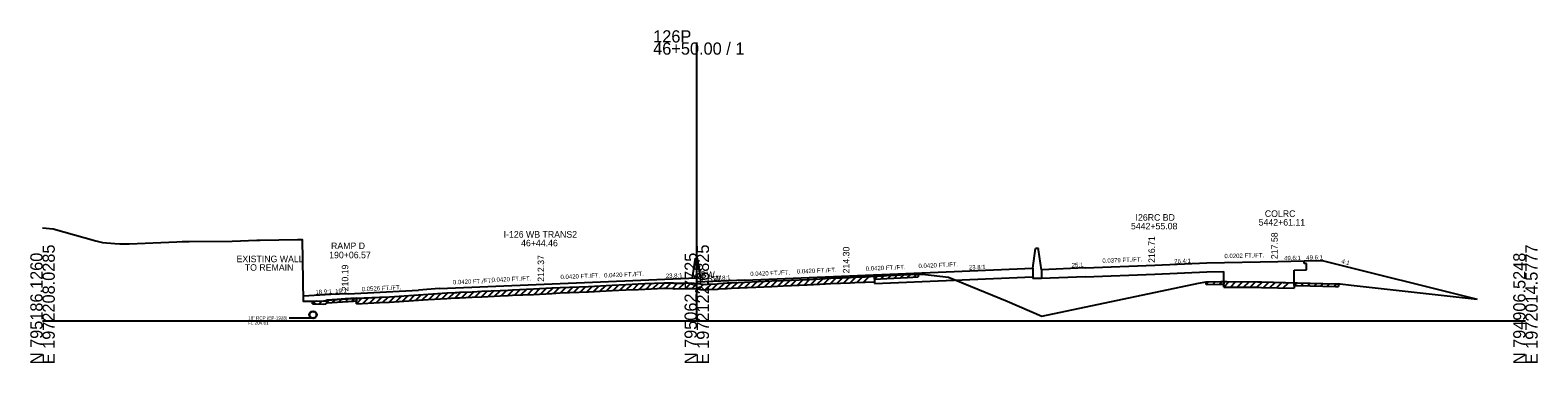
# Model space of a CAD drawing. Extents: x -161 to 1970889, y -4362 to 797231.
# Drawn here: x 997.2 to 1342.8, y 8990.3 to 9066.7 of the extents above; entities that cross this region are included whole.
import ezdxf

# ---------------------------------------------------------------- set-up
doc = ezdxf.new("R2010")
doc.units = 0
for name, color, linetype in [('RD_GPK_XS_Cell', 7, 'Continuous'), ('RD_XS_Base', 7, 'Continuous'), ('RD_XS_EarthShd', 7, 'Continuous'), ('RD_XS_ExGround', 7, 'Continuous'), ('RD_XS_ExPaveRet', 7, 'Continuous'), ('RD_XS_MedBWall', 7, 'Continuous'), ('RD_XS_Misc_Line', 7, 'Continuous'), ('RD_XS_Pave', 7, 'Continuous'), ('RD_XS_PaveOvlay', 7, 'Continuous'), ('RD_XS_PaveShd', 7, 'Continuous'), ('RD_XS_Pipe', 7, 'Continuous'), ('RD_XS_TieSlope', 7, 'Continuous'), ('RD_XS_TX_Elev_EX', 7, 'Continuous'), ('RD_XS_TX_Elev_PR', 7, 'Continuous'), ('RD_XS_TX_MkPT', 7, 'Continuous'), ('RD_XS_TX_Notes', 7, 'Continuous'), ('RD_XS_TX_Profile', 7, 'Continuous'), ('RD_XS_TX_ShdSlope', 7, 'Continuous'), ('RD_XS_TX_Slope', 7, 'Continuous'), ('RD_XS_TX_Station', 7, 'Continuous')]:
    doc.layers.add(name, color=color, linetype=linetype)

msp = doc.modelspace()

# ---------------------------------------------------------------- linework, layer by layer
at = {"layer": 'RD_GPK_XS_Cell'}
for p, q in [((1150, 9000), (1150, 9063.88)), ((1000, 9000), (1150, 9000)), ((1150, 9000), (1340, 9000))]:
    msp.add_line(p, q, dxfattribs=at)
at = {"layer": 'RD_XS_Base'}
for p, q in [((1289.3, 9013.15), (1289.3, 9013.71)), ((1289.81, 9013.16), (1289.3, 9013.15)), ((1289.81, 9011.68), (1289.81, 9013.16)), ((1190.77, 9008.51), (1209, 9009.27)), ((1209, 9009.27), (1227.03, 9010.03)), ((1239.04, 9010.07), (1229.03, 9009.67)), ((1239.04, 9010.07), (1255.06, 9010.67)), ((1255.06, 9010.67), (1266.93, 9011.21)), ((1266.93, 9011.21), (1270.86, 9011.29)), ((1286.99, 9011.62), (1289.81, 9011.68))]:
    msp.add_line(p, q, dxfattribs=at)
at = {"layer": 'RD_XS_EarthShd'}
msp.add_line((1289.3, 9013.71), (1293.37, 9013.79), dxfattribs=at)
at = {"layer": 'RD_XS_ExGround'}
msp.add_line((1300, 9008.17), (1328.89, 9004.91), dxfattribs=at)
msp.add_lwpolyline([(1000, 9021.29), (1002.44, 9021.11), (1012.25, 9018.37), (1013.76, 9017.96), (1016.57, 9017.69), (1017.75, 9017.66), (1019.86, 9017.64), (1030.77, 9018.13), (1032, 9018.18), (1033.59, 9018.19), (1043.5, 9018.23), (1049.16, 9018.49), (1049.87, 9018.5), (1058.48, 9018.67), (1058.8, 9018.67), (1059.51, 9018.67), (1059.77, 9004.49), (1060.18, 9004.49), (1060.56, 9004.48), (1061.88, 9004.45), (1062.77, 9004.52), (1064.45, 9004.45), (1064.98, 9004.53), (1065.25, 9004.71), (1067.54, 9004.85), (1071.28, 9005.11), (1077.22, 9005.41), (1079.52, 9005.51), (1083.99, 9005.8), (1088.43, 9006.11), (1092.69, 9006.37), (1094.58, 9006.49), (1094.95, 9006.5), (1095.62, 9006.52), (1098.52, 9006.65), (1100.71, 9006.74), (1104.95, 9006.94), (1106.78, 9007.02), (1107.73, 9007.07), (1112.58, 9007.29), (1116.73, 9007.52), (1118.7, 9007.62), (1125.17, 9007.88), (1130.6, 9008.15), (1133.7, 9008.3), (1136.53, 9008.43), (1138.09, 9008.5), (1142.48, 9008.71), (1143.22, 9008.69), (1144.59, 9008.67), (1144.85, 9008.59), (1147.44, 9008.65), (1148.83, 9008.67), (1150, 9008.54), (1150.88, 9008.44), (1151.59, 9008.34), (1152.48, 9008.39), (1154.79, 9008.48), (1155.08, 9008.56), (1156.94, 9008.66), (1157.96, 9008.72), (1167.23, 9009.13), (1169.84, 9009.24), (1171.73, 9009.32), (1175.32, 9009.47), (1178.25, 9009.63), (1180.76, 9009.77), (1185.19, 9009.93), (1186.24, 9009.98), (1188.63, 9010.09), (1193.6, 9010.34), (1198.3, 9010.58), (1200.77, 9010.7), (1201.76, 9010.66), (1207.74, 9010.01), (1221.16, 9004.46), (1229.15, 9001), (1265.07, 9008.61), (1266.8, 9008.95), (1270.15, 9008.98), (1270.6, 9008.98), (1271.53, 9008.98), (1278.59, 9008.91), (1279.5, 9008.89), (1287.76, 9008.67), (1296.46, 9008.48), (1297.15, 9008.47), (1297.5, 9008.45), (1300, 9008.17)], dxfattribs=at)
at = {"layer": 'RD_XS_ExPaveRet'}
for p, q in [((1178.25, 9008.38), (1180.76, 9008.52)), ((1180.76, 9008.52), (1185.19, 9008.68)), ((1185.19, 9008.68), (1186.24, 9008.73)), ((1186.24, 9008.73), (1188.63, 9008.84)), ((1188.63, 9008.84), (1190.77, 9008.95)), ((1190.77, 9010.2), (1190.77, 9008.95)), ((1190.77, 9009.57), (1190.77, 9010.2)), ((1190.77, 9009.57), (1193.6, 9009.71)), ((1193.6, 9009.71), (1198.3, 9009.95)), ((1198.3, 9009.95), (1200.77, 9010.08)), ((1200.77, 9010.7), (1200.77, 9010.08)), ((1266.8, 9008.33), (1266.8, 9008.95)), ((1270.86, 9007.73), (1270.86, 9008.98)), ((1270.86, 9008.98), (1270.86, 9008.36)), ((1286.99, 9008.69), (1286.99, 9007.44)), ((1286.99, 9008.06), (1286.99, 9008.69)), ((1297.15, 9008.47), (1297.15, 9007.84)), ((1071.95, 9003.9), (1071.95, 9005.15)), ((1071.95, 9005.15), (1071.95, 9004.52)), ((1088.43, 9004.86), (1092.69, 9005.12)), ((1092.69, 9005.12), (1094.58, 9005.24)), ((1094.58, 9005.24), (1094.95, 9005.25)), ((1094.95, 9005.25), (1095.62, 9005.27)), ((1095.62, 9005.27), (1098.52, 9005.4)), ((1098.52, 9005.4), (1100.71, 9005.49)), ((1100.71, 9005.49), (1104.95, 9005.69)), ((1104.95, 9005.69), (1106.78, 9005.77)), ((1106.78, 9005.77), (1107.73, 9005.82)), ((1107.73, 9005.82), (1112.58, 9006.04)), ((1112.58, 9006.04), (1116.73, 9006.27)), ((1116.73, 9006.27), (1118.7, 9006.37)), ((1118.7, 9006.37), (1125.17, 9006.63)), ((1125.17, 9006.63), (1130.6, 9006.9)), ((1130.6, 9006.9), (1133.7, 9007.05)), ((1133.7, 9007.05), (1136.53, 9007.18)), ((1136.53, 9007.18), (1138.09, 9007.25)), ((1138.09, 9007.25), (1142.48, 9007.46)), ((1142.48, 9007.46), (1143.22, 9007.44)), ((1143.22, 9007.44), (1144.59, 9007.42)), ((1144.59, 9007.42), (1144.85, 9007.34)), ((1144.85, 9007.34), (1147.44, 9007.4)), ((1147.44, 9007.4), (1148.83, 9007.42)), ((1148.83, 9007.42), (1150, 9007.29)), ((1150, 9007.29), (1150.88, 9007.19)), ((1150.88, 9007.19), (1151.59, 9007.09)), ((1151.59, 9007.09), (1152.48, 9007.14)), ((1152.48, 9007.14), (1154.79, 9007.23)), ((1154.79, 9007.23), (1155.08, 9007.31)), ((1155.08, 9007.31), (1156.94, 9007.41)), ((1156.94, 9007.41), (1157.96, 9007.47)), ((1157.96, 9007.47), (1167.23, 9007.88)), ((1167.23, 9007.88), (1169.84, 9007.99)), ((1169.84, 9007.99), (1171.73, 9008.07)), ((1171.73, 9008.07), (1175.32, 9008.22)), ((1175.32, 9008.22), (1178.25, 9008.38)), ((1266.8, 9008.33), (1270.15, 9008.36)), ((1270.15, 9008.36), (1270.6, 9008.36)), ((1270.6, 9008.36), (1270.86, 9008.36)), ((1270.86, 9007.73), (1271.53, 9007.73)), ((1271.53, 9007.73), (1278.59, 9007.66)), ((1278.59, 9007.66), (1279.5, 9007.64)), ((1279.5, 9007.64), (1286.99, 9007.44)), ((1286.99, 9008.06), (1287.76, 9008.04)), ((1287.76, 9008.04), (1296.46, 9007.86)), ((1296.46, 9007.86), (1297.15, 9007.84)), ((1061.88, 9003.83), (1061.88, 9004.45)), ((1061.88, 9003.83), (1062.77, 9003.89)), ((1061.88, 9003.83), (1061.88, 9003.83)), ((1062.77, 9003.89), (1064.45, 9003.82)), ((1064.45, 9003.82), (1064.98, 9003.9)), ((1064.98, 9003.9), (1065.25, 9004.08)), ((1065.25, 9004.08), (1067.54, 9004.22)), ((1067.54, 9004.22), (1071.28, 9004.49)), ((1071.28, 9004.49), (1071.95, 9004.52)), ((1071.95, 9003.9), (1077.22, 9004.16)), ((1077.22, 9004.16), (1079.52, 9004.26)), ((1079.52, 9004.26), (1083.99, 9004.55)), ((1083.99, 9004.55), (1088.43, 9004.86))]:
    msp.add_line(p, q, dxfattribs=at)
at = {"layer": 'RD_XS_MedBWall'}
for p, q in [((1227.03, 9012.07), (1227.7, 9016.61)), ((1228.36, 9016.61), (1227.7, 9016.61)), ((1228.36, 9016.23), (1228.36, 9016.61)), ((1229.03, 9011.69), (1228.36, 9016.23)), ((1149, 9009.8), (1149.67, 9014.34)), ((1149.67, 9014.34), (1150.18, 9014.34)), ((1151, 9008.88), (1150.18, 9014.34)), ((1227.03, 9012.07), (1227.03, 9009.65)), ((1229.03, 9009.65), (1227.03, 9009.65)), ((1229.03, 9011.69), (1229.03, 9009.65))]:
    msp.add_line(p, q, dxfattribs=at)
at = {"layer": 'RD_XS_Misc_Line'}
for p, q in [((1136.86, 9007.2), (1138.18, 9008.51)), ((1138.37, 9007.26), (1139.69, 9008.58)), ((1139.88, 9007.34), (1141.2, 9008.65)), ((1141.39, 9007.41), (1142.69, 9008.7)), ((1142.9, 9007.45), (1144.13, 9008.68)), ((1144.41, 9007.42), (1145.6, 9008.61)), ((1145.92, 9007.36), (1147.2, 9008.64)), ((1147.43, 9007.4), (1148.71, 9008.67)), ((1148.94, 9007.41), (1150.06, 9008.53)), ((1153.46, 9007.18), (1154.77, 9008.48)), ((1154.97, 9007.28), (1156.33, 9008.63)), ((1156.48, 9007.39), (1157.82, 9008.72)), ((1157.99, 9007.47), (1159.31, 9008.78)), ((1159.5, 9007.54), (1160.82, 9008.85)), ((1161.01, 9007.61), (1162.33, 9008.91)), ((1162.52, 9007.67), (1163.84, 9008.98)), ((1164.03, 9007.74), (1165.35, 9009.05)), ((1165.54, 9007.8), (1166.86, 9009.11)), ((1167.05, 9007.87), (1168.37, 9009.18)), ((1168.56, 9007.94), (1169.88, 9009.25)), ((1170.07, 9008), (1171.38, 9009.3)), ((1171.58, 9008.06), (1172.89, 9009.36)), ((1173.09, 9008.12), (1174.4, 9009.43)), ((1174.6, 9008.19), (1175.92, 9009.5)), ((1176.11, 9008.26), (1177.44, 9009.59)), ((1177.62, 9008.35), (1178.95, 9009.67)), ((1179.13, 9008.43), (1180.46, 9009.75)), ((1180.64, 9008.51), (1181.95, 9009.81)), ((1182.15, 9008.57), (1183.45, 9009.87)), ((1183.66, 9008.62), (1184.96, 9009.92)), ((1185.17, 9008.68), (1186.48, 9009.99)), ((1186.68, 9008.75), (1188, 9010.06)), ((1188.19, 9008.82), (1189.51, 9010.14)), ((1190.77, 9009.57), (1191.43, 9010.23)), ((1192.28, 9009.65), (1192.94, 9010.3)), ((1193.79, 9009.72), (1194.46, 9010.38)), ((1195.3, 9009.8), (1195.97, 9010.46)), ((1196.81, 9009.88), (1197.48, 9010.54)), ((1198.32, 9009.96), (1198.98, 9010.61)), ((1199.83, 9010.03), (1200.49, 9010.69)), ((1266.8, 9008.33), (1267.44, 9008.96)), ((1268.31, 9008.34), (1268.95, 9008.97)), ((1269.82, 9008.36), (1270.45, 9008.98)), ((1270.86, 9007.73), (1272.1, 9008.97)), ((1272.37, 9007.72), (1273.61, 9008.96)), ((1273.88, 9007.7), (1275.12, 9008.94)), ((1275.39, 9007.69), (1276.63, 9008.93)), ((1276.9, 9007.68), (1278.14, 9008.91)), ((1278.41, 9007.66), (1279.63, 9008.88)), ((1279.91, 9007.63), (1281.14, 9008.84)), ((1281.42, 9007.59), (1282.65, 9008.8)), ((1282.93, 9007.55), (1284.16, 9008.76)), ((1284.44, 9007.51), (1285.67, 9008.72)), ((1286.99, 9008.06), (1287.61, 9008.67)), ((1288.5, 9008.03), (1289.12, 9008.64)), ((1290.01, 9008), (1290.63, 9008.61)), ((1291.52, 9007.96), (1292.14, 9008.57)), ((1293.03, 9007.93), (1293.65, 9008.54)), ((1294.54, 9007.9), (1295.16, 9008.51)), ((1296.05, 9007.86), (1296.67, 9008.48)), ((1069.43, 9004.36), (1070.11, 9005.03)), ((1070.94, 9004.46), (1071.61, 9005.13)), ((1071.95, 9003.9), (1073.27, 9005.21)), ((1073.45, 9003.97), (1074.78, 9005.29)), ((1074.96, 9004.05), (1076.29, 9005.36)), ((1076.47, 9004.12), (1077.8, 9005.43)), ((1077.98, 9004.19), (1079.3, 9005.5)), ((1079.49, 9004.26), (1080.84, 9005.6)), ((1081, 9004.36), (1082.35, 9005.7)), ((1082.51, 9004.46), (1083.86, 9005.79)), ((1084.02, 9004.56), (1085.37, 9005.9)), ((1085.53, 9004.66), (1086.88, 9006)), ((1087.04, 9004.76), (1088.39, 9006.1)), ((1088.55, 9004.86), (1089.89, 9006.2)), ((1090.06, 9004.96), (1091.4, 9006.29)), ((1091.57, 9005.05), (1092.91, 9006.39)), ((1093.08, 9005.15), (1094.42, 9006.48)), ((1094.59, 9005.25), (1095.88, 9006.53)), ((1096.1, 9005.29), (1097.42, 9006.6)), ((1097.61, 9005.36), (1098.93, 9006.67)), ((1099.12, 9005.43), (1100.43, 9006.73)), ((1100.63, 9005.49), (1101.95, 9006.8)), ((1102.14, 9005.56), (1103.46, 9006.87)), ((1103.65, 9005.63), (1104.97, 9006.94)), ((1105.16, 9005.7), (1106.47, 9007.01)), ((1106.67, 9005.76), (1107.99, 9007.08)), ((1108.18, 9005.84), (1109.49, 9007.15)), ((1109.69, 9005.9), (1111, 9007.21)), ((1111.2, 9005.97), (1112.51, 9007.28)), ((1112.71, 9006.04), (1114.04, 9007.37)), ((1114.21, 9006.13), (1115.55, 9007.45)), ((1115.72, 9006.21), (1117.06, 9007.53)), ((1117.23, 9006.29), (1118.56, 9007.61)), ((1118.74, 9006.37), (1120.05, 9007.67)), ((1120.25, 9006.43), (1121.56, 9007.73)), ((1121.76, 9006.49), (1123.07, 9007.8)), ((1123.27, 9006.55), (1124.58, 9007.86)), ((1124.78, 9006.61), (1126.1, 9007.93)), ((1126.29, 9006.69), (1127.62, 9008)), ((1127.8, 9006.76), (1129.12, 9008.07)), ((1129.31, 9006.83), (1130.63, 9008.15)), ((1130.82, 9006.91), (1132.14, 9008.22)), ((1132.33, 9006.98), (1133.65, 9008.29)), ((1133.84, 9007.05), (1135.16, 9008.36)), ((1135.35, 9007.12), (1136.67, 9008.44)), ((1150.45, 9007.24), (1151.56, 9008.35)), ((1151.96, 9007.11), (1153.27, 9008.42)), ((1061.88, 9003.83), (1062.56, 9004.5)), ((1063.39, 9003.87), (1063.99, 9004.47)), ((1064.9, 9003.89), (1065.75, 9004.74)), ((1066.41, 9004.15), (1067.08, 9004.82)), ((1067.92, 9004.25), (1068.6, 9004.92))]:
    msp.add_line(p, q, dxfattribs=at)
at = {"layer": 'RD_XS_Pave'}
for p, q in [((1239.04, 9012.11), (1255.06, 9012.71)), ((1266.93, 9013.25), (1283.2, 9013.58)), ((1115, 9008.37), (1139, 9009.38)), ((1161, 9009.3), (1185, 9010.3)), ((1185, 9010.3), (1209, 9011.31)), ((1070.11, 9006.19), (1086.19, 9007.04)), ((1091, 9007.36), (1115, 9008.37))]:
    msp.add_line(p, q, dxfattribs=at)
at = {"layer": 'RD_XS_PaveOvlay'}
for p, q in [((1136.53, 9008.43), (1138.09, 9008.5)), ((1138.09, 9008.5), (1142.48, 9008.71)), ((1142.48, 9008.71), (1143.22, 9008.69)), ((1143.22, 9008.69), (1144.59, 9008.67)), ((1144.59, 9008.67), (1144.85, 9008.59)), ((1144.85, 9008.59), (1147.44, 9008.65)), ((1147.44, 9008.65), (1148.83, 9008.67)), ((1148.83, 9008.67), (1150, 9008.54)), ((1150, 9008.54), (1150.88, 9008.44)), ((1152.48, 9008.39), (1154.79, 9008.48)), ((1154.79, 9008.48), (1155.08, 9008.56)), ((1155.08, 9008.56), (1156.94, 9008.66)), ((1156.94, 9008.66), (1157.96, 9008.72)), ((1157.96, 9008.72), (1167.23, 9009.13)), ((1167.23, 9009.13), (1169.84, 9009.24)), ((1169.84, 9009.24), (1171.73, 9009.32)), ((1171.73, 9009.32), (1175.32, 9009.47)), ((1175.32, 9009.47), (1178.25, 9009.63)), ((1178.25, 9009.63), (1180.76, 9009.77)), ((1180.76, 9009.77), (1185.19, 9009.93)), ((1185.19, 9009.93), (1186.24, 9009.98)), ((1186.24, 9009.98), (1188.63, 9010.09)), ((1188.63, 9010.09), (1190.77, 9010.2)), ((1190.77, 9010.2), (1190.77, 9008.51)), ((1270.86, 9008.98), (1270.86, 9011.29)), ((1286.99, 9008.69), (1286.99, 9011.62)), ((1059.75, 9005.64), (1059.77, 9004.49)), ((1071.95, 9005.15), (1069.41, 9004.98)), ((1071.95, 9005.15), (1077.22, 9005.41)), ((1077.22, 9005.41), (1079.52, 9005.51)), ((1079.52, 9005.51), (1083.99, 9005.8)), ((1083.99, 9005.8), (1088.43, 9006.11)), ((1088.43, 9006.11), (1092.69, 9006.37)), ((1092.69, 9006.37), (1094.58, 9006.49)), ((1094.58, 9006.49), (1094.95, 9006.5)), ((1094.95, 9006.5), (1095.62, 9006.52)), ((1095.62, 9006.52), (1098.52, 9006.65)), ((1098.52, 9006.65), (1100.71, 9006.74)), ((1100.71, 9006.74), (1104.95, 9006.94)), ((1104.95, 9006.94), (1106.78, 9007.02)), ((1106.78, 9007.02), (1107.73, 9007.07)), ((1107.73, 9007.07), (1112.58, 9007.29)), ((1112.58, 9007.29), (1116.73, 9007.52)), ((1116.73, 9007.52), (1118.7, 9007.62)), ((1118.7, 9007.62), (1125.17, 9007.88)), ((1125.17, 9007.88), (1130.6, 9008.15)), ((1130.6, 9008.15), (1133.7, 9008.3)), ((1133.7, 9008.3), (1136.53, 9008.43)), ((1150.88, 9008.44), (1151.59, 9008.34)), ((1151.59, 9008.34), (1152.48, 9008.39)), ((1059.77, 9004.49), (1061.88, 9004.45)), ((1061.88, 9004.45), (1062.77, 9004.52)), ((1062.77, 9004.52), (1064.45, 9004.45)), ((1064.98, 9004.53), (1064.45, 9004.45)), ((1065.25, 9004.71), (1064.98, 9004.53)), ((1066.4, 9004.78), (1065.25, 9004.71)), ((1067.54, 9004.85), (1066.4, 9004.78)), ((1069.41, 9004.98), (1067.54, 9004.85))]:
    msp.add_line(p, q, dxfattribs=at)
msp.add_lwpolyline([(1270.86, 9008.98), (1271.53, 9008.98), (1278.59, 9008.91), (1279.5, 9008.89), (1286.99, 9008.69)], dxfattribs=at)
at = {"layer": 'RD_XS_PaveShd'}
for p, q in [((1209, 9011.31), (1227.03, 9012.07)), ((1239.04, 9012.11), (1229.03, 9011.71)), ((1255.06, 9012.71), (1266.93, 9013.25)), ((1283.2, 9013.58), (1289.3, 9013.71)), ((1139, 9009.38), (1150, 9009.84)), ((1150, 9008.83), (1150, 9009.84)), ((1161, 9009.3), (1150, 9008.83)), ((1066.08, 9005.98), (1059.75, 9005.64)), ((1070.11, 9006.19), (1066.08, 9005.98)), ((1091, 9007.36), (1086.19, 9007.04))]:
    msp.add_line(p, q, dxfattribs=at)
at = {"layer": 'RD_XS_Pipe'}
msp.add_line((1061.51, 9000.61), (1056.51, 9000.61), dxfattribs=at)
for radius in [0.85, 0.75]:
    msp.add_circle((1062.01, 9001.36), radius, dxfattribs=at)
at = {"layer": 'RD_XS_TieSlope'}
msp.add_line((1293.37, 9013.79), (1328.89, 9004.91), dxfattribs=at)

# ---------------------------------------------------------------- texts
at = {"layer": 'RD_GPK_XS_Cell'}
for s, p in [('46+50.00 / 1', (1140, 9061.08)), ('126P', (1140, 9063.88))]:
    msp.add_text(s, height=2.8, dxfattribs=at).set_placement(p)
for s, p in [('N 795186.1260', (1000, 8990)), ('E 1972208.0285', (1002.8, 8990)), ('N 795062.7725', (1150, 8990)), ('E 1972122.6825', (1152.8, 8990)), ('N 794906.5248', (1340, 8990)), ('E 1972014.5777', (1342.8, 8990))]:
    msp.add_text(s, height=2.8, rotation=90, dxfattribs=at).set_placement(p)
at = {"layer": 'RD_XS_Pipe'}
for s, p in [('18" RCP (EP-1928)', (1047.15, 9000.24)), ('FL 204.61', (1047.15, 8999.11))]:
    msp.add_text(s, height=0.75, dxfattribs=at).set_placement(p)
at = {"layer": 'RD_XS_TX_Elev_EX'}
msp.add_text('212.54', height=1, rotation=90, dxfattribs=at).set_placement((1151, 9008.54))
at = {"layer": 'RD_XS_TX_Elev_PR'}
for s, p in [(' 216.71', (1255.06, 9012.71)), (' 217.58', (1283.2, 9013.58)), (' 214.30', (1185, 9010.3)), (' 210.19', (1070.11, 9006.19)), (' 212.37', (1115, 9008.37))]:
    msp.add_text(s, height=1.5, rotation=90, dxfattribs=at).set_placement(p)
at = {"layer": 'RD_XS_TX_MkPT'}
for s, p in [('WBW', (1149, 9009.8)), ('EBW', (1151, 9008.88))]:
    msp.add_text(s, height=1.5, dxfattribs=at).set_placement(p)
at = {"layer": 'RD_XS_TX_Notes'}
for s, p in [('EXISTING WALL', (1044.48, 9013.43)), ('TO REMAIN', (1046.37, 9011.47))]:
    msp.add_text(s, height=1.5, dxfattribs=at).set_placement(p)
at = {"layer": 'RD_XS_TX_Profile'}
for s, rotation, p in [('23.8:1', 2.405, (1212.41, 9011.71)), ('26.4:1', 2.1678, (1259.48, 9013.13)), ('23.8:1', 2.405, (1142.91, 9009.79)), ('23.8:1', 2.405, (1153.91, 9009.25))]:
    msp.add_text(s, height=1, rotation=rotation, dxfattribs=at).set_placement(p)
at = {"layer": 'RD_XS_TX_ShdSlope'}
msp.add_text('49.6:1', height=1, rotation=1.1545, dxfattribs=at).set_placement((1289.75, 9013.97))
at = {"layer": 'RD_XS_TX_Slope'}
for s, rotation, p in [('0.0202 FT./FT.', 1.1545, (1270.98, 9014.34)), ('0.0420 FT./FT.', 2.405, (1172.96, 9010.8)), ('0.0420 FT./FT.', 2.405, (1188.77, 9011.46)), ('0.0420 FT./FT.', 2.405, (1200.85, 9012.07)), ('25:1', 2.2877, (1235.98, 9012.24)), ('0.0379 FT./FT.', 2.1678, (1243.01, 9013.26)), ('49.6:1', 1.1545, (1284.67, 9013.86)), ('4:1', 344.1175, (1297.7, 9013.24)), ('0.0420 FT./FT.', 2.405, (1094.11, 9008.32)), ('0.0420 FT./FT.', 2.405, (1102.96, 9008.87)), ('0.0420 FT./FT.', 2.405, (1118.77, 9009.53)), ('0.0420 FT./FT.', 2.405, (1128.77, 9009.9)), ('0.0420 FT./FT.', 2.405, (1162.28, 9010.22)), ('18.9:1', 3.0211, (1062.59, 9006.04)), ('19:1', 3.0102, (1067.12, 9006.28)), ('0.0526 FT./FT.', 3.0106, (1073.2, 9006.74))]:
    msp.add_text(s, height=1, rotation=rotation, dxfattribs=at).set_placement(p)
at = {"layer": 'RD_XS_TX_Station'}
for s, p in [('5442+55.08', (1249.55, 9020.96)), ('I26RC BD', (1250.6, 9022.96)), ('5442+61.11', (1278.83, 9021.83)), ('COLRC', (1280.24, 9023.83)), ('I-126 WB TRANS2', (1105.72, 9019.07)), ('190+06.57', (1065.72, 9014.33)), ('RAMP D', (1066.14, 9016.44)), ('46+44.46', (1109.72, 9017.07))]:
    msp.add_text(s, height=1.5, dxfattribs=at).set_placement(p)

doc.saveas('drawing.dxf')
